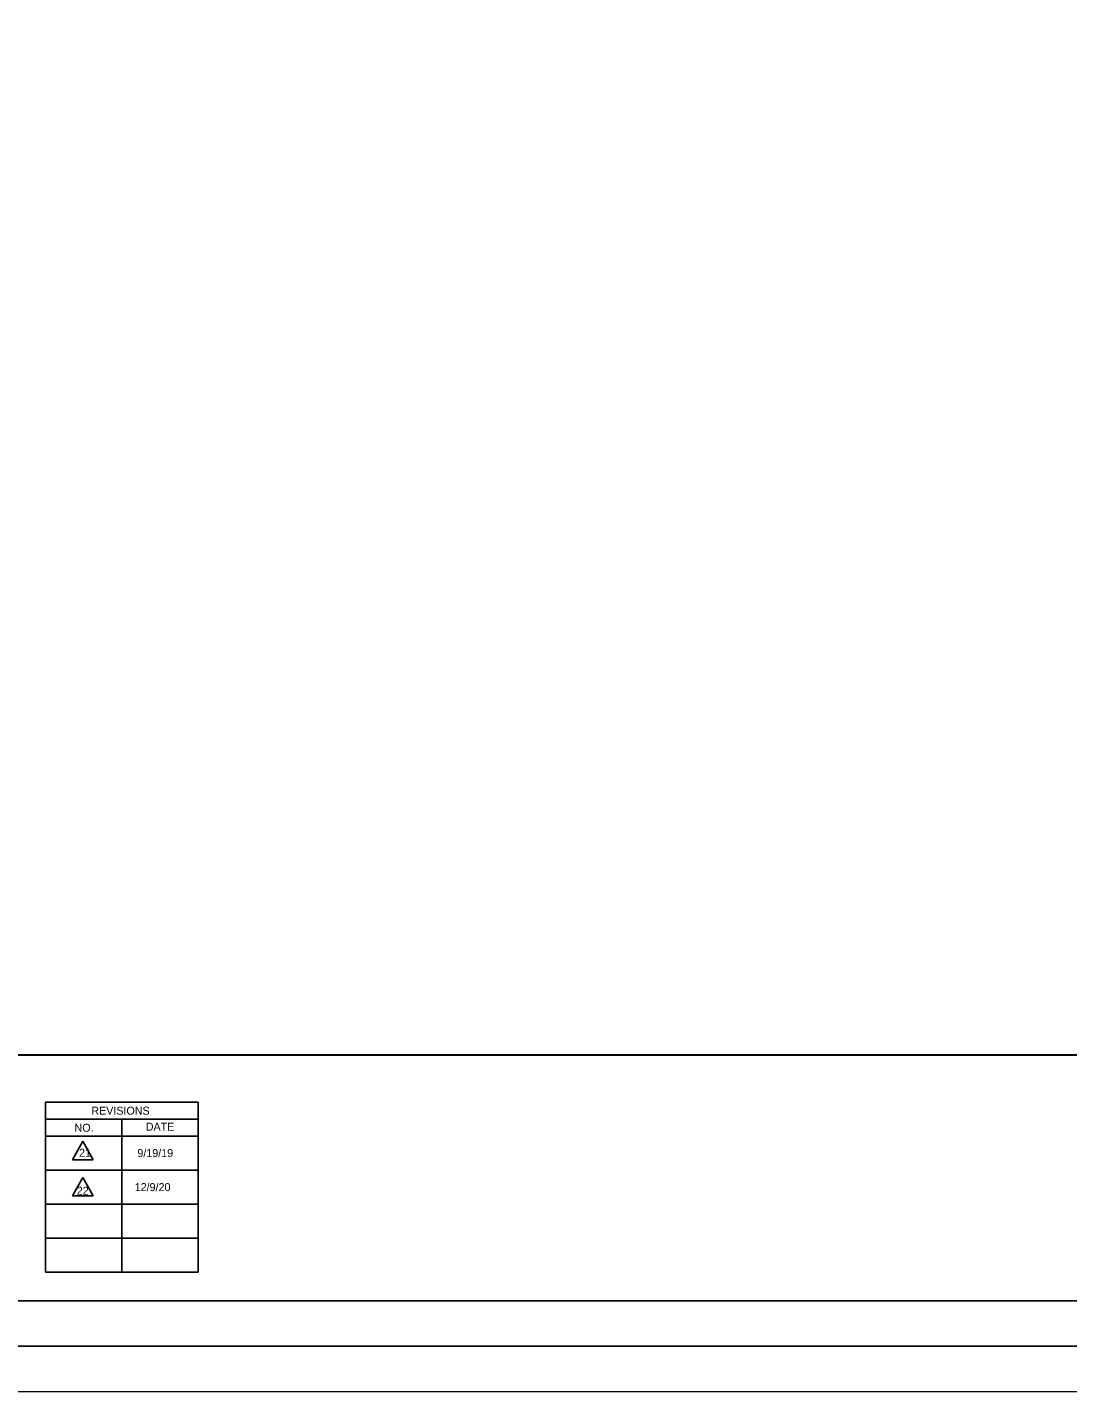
# Model space of a CAD drawing. Extents: x -2251 to 10196, y -13470 to 1199.
# Drawn here: x 5664 to 6236, y -11951 to -11201 of the extents above; entities that cross this region are included whole.
import ezdxf

# ---------------------------------------------------------------- set-up
doc = ezdxf.new("R2010")
doc.units = 0
for name, color, linetype in [('RD_SHT_Bndy', 7, 'Continuous'), ('RD_SHT_Iplotshp', 7, 'Continuous'), ('RD_SHT_Misc1', 7, 'Continuous'), ('RD_SHT_Snap', 7, 'Continuous'), ('RD_SHT_TX', 7, 'Continuous'), ('RD_TX_RoadID', 7, 'Continuous')]:
    doc.layers.add(name, color=color, linetype=linetype)

msp = doc.modelspace()

# ---------------------------------------------------------------- linework, layer by layer
at = {"layer": 'RD_SHT_Bndy'}
for p, q in [((5103.1, -11900.65), (6778.1, -11900.65)), ((6050.94, -11900.65), (5836.06, -11900.65)), ((6791.65, -11925.65), (5031.65, -11925.65)), ((6791.6, -11950.7), (5031.6, -11950.65))]:
    msp.add_line(p, q, dxfattribs=at)
msp.add_lwpolyline([(5153.4, -10901.26), (6731.08, -10901.26), (6731.08, -11765.57), (5153.4, -11765.57)], close=True, dxfattribs=at)
at = {"layer": 'RD_SHT_Iplotshp'}
msp.add_lwpolyline([(4996.65, -10825.65), (6796.65, -10825.65), (6796.65, -11925.65), (4996.65, -11925.65)], close=True, dxfattribs=at)
at = {"layer": 'RD_SHT_Misc1'}
msp.add_lwpolyline([(6796.65, -11925.65), (6796.68, -10825.65), (5096.68, -10825.6), (5096.65, -11925.6)], close=True, dxfattribs=at)
at = {"layer": 'RD_SHT_Snap'}
msp.add_lwpolyline([(5008.15, -10825.65), (6808.15, -10825.65), (6808.15, -11925.65), (5008.15, -11925.65)], close=True, dxfattribs=at)
at = {"layer": 'RD_SHT_TX'}
for p, q in [((5757.89, -11791.56), (5673.89, -11791.56)), ((5673.89, -11791.56), (5673.89, -11885.05)), ((5757.89, -11885.05), (5757.89, -11791.56)), ((5757.89, -11800.91), (5673.89, -11800.91)), ((5715.89, -11885.05), (5715.89, -11800.91)), ((5757.89, -11810.25), (5673.89, -11810.25)), ((5694.45, -11813.04), (5688.75, -11823.18)), ((5694.45, -11813.04), (5700.14, -11823.18)), ((5688.75, -11823.18), (5700.14, -11823.18)), ((5757.89, -11828.95), (5673.89, -11828.95)), ((5694.45, -11832.93), (5688.75, -11843.07)), ((5694.45, -11832.93), (5700.14, -11843.07)), ((5757.89, -11847.65), (5673.89, -11847.65)), ((5688.75, -11843.07), (5700.14, -11843.07)), ((5757.89, -11866.35), (5673.89, -11866.35)), ((5757.89, -11885.05), (5673.89, -11885.05))]:
    msp.add_line(p, q, dxfattribs=at)
at = {"layer": 'RD_TX_RoadID'}
msp.add_lwpolyline([(5150.54, -11765.73), (6733.93, -11765.73), (6733.93, -10962.61), (5150.54, -10962.61)], close=True, dxfattribs=at)

# ---------------------------------------------------------------- texts
at = {"layer": 'RD_SHT_TX'}
for s, height, rotation, p in [('REVISIONS', 4.4, 360, (5699.18, -11798.43)), ('NO.', 4.4, 360, (5689.92, -11807.78)), ('DATE', 4.408, 359.72458, (5729.08, -11807.19))]:
    msp.add_text(s, height=height, rotation=rotation, dxfattribs=at).set_placement(p)
for s, p in [('21', (5692.43, -11821.54)), ('9/19/19', (5724.49, -11821.72)), ('22', (5691.15, -11842.42)), ('12/9/20', (5723.03, -11840.42))]:
    msp.add_text(s, height=4.4, dxfattribs=at).set_placement(p)

doc.saveas('drawing.dxf')
